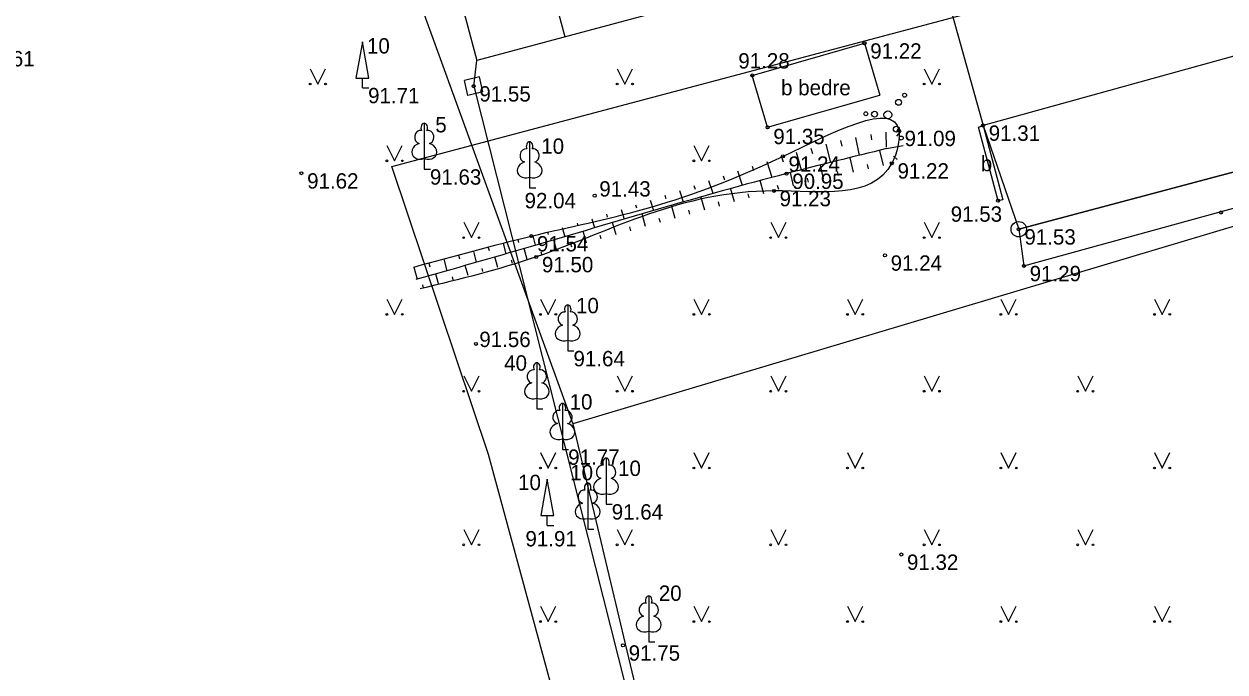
# Model space of a CAD drawing. Extents: x 634272 to 634544, y 247463 to 247653.
# Drawn here: x 634375.43 to 634414.55, y 247510.86 to 247531.95 of the extents above; entities that cross this region are included whole.
import ezdxf

# ---------------------------------------------------------------- set-up
doc = ezdxf.new("R2010")
doc.units = 0
for name, color, linetype in [('BUVE_BALK_####_####_#', 7, 'Continuous'), ('BUVE_BDET_####_####_#', 7, 'Continuous'), ('BUVE_BDET_####_TKST_#', 7, 'Continuous'), ('BUVE_EKAS_####_####_#', 7, 'Continuous'), ('BUVE_ELEM_####_####_#', 7, 'Continuous'), ('NORB_ELEM_####_####_#', 7, 'Continuous'), ('NORB_ZOGS_SBST_####_#', 7, 'Continuous'), ('NORB_ZOGS_ZSTP_####_#', 7, 'Continuous'), ('RAMI_UZMR_####_####_#', 7, 'Continuous'), ('RELJ_AATZ_####_TKST_#', 7, 'Continuous'), ('RELJ_ELEM_####_####_#', 7, 'Continuous'), ('RELJ_NOGA_####_####_#', 7, 'Continuous'), ('RELJ_NOGL_####_####_#', 7, 'Continuous'), ('ROBZ_PROJ_####_####_#', 7, 'Continuous'), ('ROBZ_UZMR_####_####_#', 7, 'Continuous'), ('TERT_DIAM_####_TKST_#', 7, 'Continuous'), ('TERT_ELEM_####_####_#', 7, 'Continuous')]:
    doc.layers.add(name, color=color, linetype=linetype)

msp = doc.modelspace()

# ---------------------------------------------------------------- linework, layer by layer
at = {"layer": 'BUVE_BALK_####_####_#'}
for points in [[(634407.83, 247525.273), (634432.599, 247531.864)], [(634406.667, 247528.651), (634407.83, 247525.273)]]:
    msp.add_lwpolyline(points, dxfattribs=at)
at = {"layer": 'BUVE_BDET_####_####_#'}
for p in [(634402.807, 247531.326), (634399.65, 247528.593)]:
    msp.add_line(p, (634403.305, 247529.64), dxfattribs=at)
for points in [[(634408.001, 247524.08), (634432.864, 247530.914), (634432.599, 247531.864), (634407.83, 247525.273), (634408.001, 247524.08)], [(634399.65, 247528.593), (634399.152, 247530.279), (634402.807, 247531.326)], [(634406.667, 247528.651), (634407.314, 247526.226), (634407.157, 247526.202), (634406.522, 247528.597), (634406.667, 247528.651)]]:
    msp.add_lwpolyline(points, dxfattribs=at)
at = {"layer": 'BUVE_EKAS_####_####_#'}
for q in [(634390.179, 247530.767), (634406.667, 247528.651)]:
    msp.add_line((634404.984, 247534.73), q, dxfattribs=at)
for points in [[(634427.366, 247549.085), (634431.438, 247535.508), (634406.667, 247528.651)], [(634390.958, 247539.332), (634393.045, 247531.534)], [(634388.101, 247538.53), (634390.179, 247530.767)]]:
    msp.add_lwpolyline(points, dxfattribs=at)
at = {"layer": 'BUVE_ELEM_####_####_#'}
msp.add_circle((634407.83, 247525.273), 0.25, dxfattribs=at)
at = {"layer": 'NORB_ELEM_####_####_#'}
for p, q in [((634390.262, 247530.231), (634389.775, 247530.116)), ((634390.377, 247529.744), (634390.262, 247530.231)), ((634389.89, 247529.629), (634389.775, 247530.116)), ((634390.377, 247529.744), (634389.89, 247529.629))]:
    msp.add_line(p, q, dxfattribs=at)
msp.add_circle((634390.076, 247529.93), 0.0504, dxfattribs=at)
at = {"layer": 'NORB_ZOGS_SBST_####_#'}
msp.add_lwpolyline([(634390.076, 247529.93), (634397.008, 247502.541)], dxfattribs=at)
at = {"layer": 'NORB_ZOGS_ZSTP_####_#'}
msp.add_lwpolyline([(634390.076, 247529.93), (634390.179, 247530.767)], dxfattribs=at)
at = {"layer": 'RAMI_UZMR_####_####_#'}
msp.add_lwpolyline([(634466.614, 247558.36), (634469.076, 247546.545), (634471.781, 247533.982), (634471.429, 247521.859), (634457.577, 247518.735), (634456.257, 247517.942), (634433.742, 247506.986), (634428.158, 247503.509), (634420.457, 247500.517), (634407.71, 247496.821), (634397.043, 247493.687), (634395.968, 247498.053), (634390.559, 247517.942), (634387.41, 247527.318), (634427.834, 247538.059), (634425.364, 247546.393), (634376.048, 247532.596), (634371.988, 247530.992)], dxfattribs=at)
at = {"layer": 'RELJ_ELEM_####_####_#'}
for centre in [(634402.807, 247531.326), (634399.152, 247530.279), (634390.076, 247529.93), (634399.65, 247528.593), (634406.667, 247528.651), (634403.925, 247528.48), (634400.145, 247527.645), (634403.696, 247527.422), (634384.465, 247527.096), (634400.267, 247527.085), (634394.019, 247526.366), (634399.854, 247526.521), (634407.157, 247526.202), (634414.415, 247525.819), (634391.952, 247525.05), (634407.83, 247525.273), (634392.113, 247524.371), (634403.472, 247524.422), (634408.001, 247524.08), (634390.147, 247521.54), (634404.004, 247514.685), (634394.939, 247511.728)]:
    msp.add_circle(centre, 0.05, dxfattribs=at)
at = {"layer": 'RELJ_NOGA_####_####_#'}
for p, q in [((634402.517, 247528.264), (634402.636, 247527.676)), ((634403.009, 247528.356), (634403.037, 247528.187)), ((634403.503, 247528.431), (634403.512, 247527.946)), ((634403.861, 247528.301), (634403.998, 247528.468)), ((634403.953, 247528.48), (634403.953, 247528.48)), ((634401.059, 247527.914), (634401.108, 247527.737)), ((634401.542, 247528.042), (634401.695, 247527.441)), ((634402.028, 247528.159), (634402.069, 247527.979)), ((634403.422, 247527.352), (634403.301, 247527.841)), ((634403.524, 247527.897), (634404.068, 247528.001)), ((634404.078, 247528.047), (634404.077, 247528.047)), ((634399.623, 247527.48), (634399.788, 247526.964)), ((634400.1, 247527.631), (634400.152, 247527.467)), ((634400.578, 247527.777), (634400.748, 247527.205)), ((634402.448, 247527.127), (634402.343, 247527.603)), ((634403.869, 247527.547), (634403.747, 247527.648)), ((634403.897, 247527.585), (634403.897, 247527.585)), ((634398.672, 247527.17), (634398.824, 247526.709)), ((634399.148, 247527.326), (634399.195, 247527.18)), ((634400.496, 247526.688), (634400.392, 247527.116)), ((634401.471, 247526.912), (634401.372, 247527.361)), ((634401.959, 247527.02), (634401.929, 247527.158)), ((634402.935, 247527.236), (634402.902, 247527.382)), ((634397.249, 247526.696), (634397.288, 247526.58)), ((634397.723, 247526.855), (634397.861, 247526.443)), ((634398.198, 247527.013), (634398.241, 247526.882)), ((634399.53, 247526.431), (634399.409, 247526.865)), ((634400.012, 247526.564), (634399.977, 247526.692)), ((634400.983, 247526.804), (634400.953, 247526.934)), ((634396.301, 247526.38), (634396.336, 247526.274)), ((634396.775, 247526.538), (634396.898, 247526.169)), ((634397.603, 247525.894), (634397.48, 247526.336)), ((634398.567, 247526.163), (634398.443, 247526.605)), ((634399.048, 247526.297), (634399.012, 247526.429)), ((634394.875, 247525.913), (634394.974, 247525.603)), ((634395.351, 247526.067), (634395.382, 247525.97)), ((634395.826, 247526.222), (634395.936, 247525.888)), ((634396.64, 247525.626), (634396.519, 247526.059)), ((634397.122, 247525.76), (634397.085, 247525.892)), ((634398.085, 247526.029), (634398.048, 247526.162)), ((634393.442, 247525.47), (634393.469, 247525.381)), ((634393.921, 247525.614), (634394.012, 247525.317)), ((634394.398, 247525.762), (634394.427, 247525.671)), ((634394.713, 247525.09), (634394.601, 247525.492)), ((634395.677, 247525.358), (634395.56, 247525.776)), ((634396.158, 247525.492), (634396.123, 247525.62)), ((634392.481, 247525.193), (634392.506, 247525.102)), ((634392.962, 247525.329), (634393.048, 247525.031)), ((634393.75, 247524.822), (634393.643, 247525.207)), ((634394.231, 247524.956), (634394.199, 247525.074)), ((634395.195, 247525.224), (634395.161, 247525.347)), ((634390.548, 247524.68), (634390.575, 247524.576)), ((634391.032, 247524.807), (634391.12, 247524.473)), ((634391.515, 247524.935), (634391.541, 247524.838)), ((634391.999, 247525.062), (634392.082, 247524.75)), ((634392.786, 247524.556), (634392.684, 247524.925)), ((634393.268, 247524.689), (634393.237, 247524.802)), ((634389.098, 247524.297), (634389.197, 247523.921)), ((634389.581, 247524.425), (634389.61, 247524.315)), ((634390.065, 247524.552), (634390.158, 247524.197)), ((634390.857, 247524.026), (634390.763, 247524.371)), ((634391.822, 247524.291), (634391.724, 247524.647)), ((634392.304, 247524.423), (634392.274, 247524.532)), ((634388.131, 247524.042), (634388.236, 247523.645)), ((634388.614, 247524.17), (634388.645, 247524.054)), ((634389.893, 247523.762), (634389.801, 247524.095)), ((634390.375, 247523.894), (634390.347, 247523.996)), ((634391.339, 247524.159), (634391.311, 247524.264)), ((634388.928, 247523.497), (634388.84, 247523.819)), ((634389.411, 247523.629), (634389.384, 247523.728)), ((634388.446, 247523.365), (634388.42, 247523.459))]:
    msp.add_line(p, q, dxfattribs=at)
msp.add_spline([(634388.131, 247524.042), (634391.952, 247525.05), (634400.145, 247527.645), (634403.925, 247528.48), (634403.696, 247527.422), (634399.854, 247526.521), (634392.113, 247524.371), (634388.335, 247523.334)], degree=3, dxfattribs=at)
at = {"layer": 'RELJ_NOGL_####_####_#'}
msp.add_spline([(634403.524, 247527.897), (634400.267, 247527.085), (634391.92, 247524.703), (634388.194, 247523.633)], degree=3, dxfattribs=at)
at = {"layer": 'ROBZ_PROJ_####_####_#'}
msp.add_lwpolyline([(634393.309, 247518.933), (634397.146, 247502.796)], dxfattribs=at)
at = {"layer": 'ROBZ_UZMR_####_####_#'}
for points in [[(634385.149, 247541.391), (634393.309, 247518.933)], [(634435.861, 247531.644), (634393.309, 247518.933)]]:
    msp.add_lwpolyline(points, dxfattribs=at)
at = {"layer": 'TERT_ELEM_####_####_#'}
for p, q in [((634384.75, 247530.5), (634385, 247530)), ((634385, 247530), (634385.25, 247530.5)), ((634386.451, 247529.875), (634386.451, 247530.195)), ((634394.75, 247530.5), (634395, 247530)), ((634395, 247530), (634395.25, 247530.5)), ((634404.75, 247530.5), (634405, 247530)), ((634405, 247530), (634405.25, 247530.5)), ((634386.451, 247529.875), (634386.661, 247529.875)), ((634387.25, 247528), (634387.5, 247527.5)), ((634387.5, 247527.5), (634387.75, 247528)), ((634397.25, 247528), (634397.5, 247527.5)), ((634397.5, 247527.5), (634397.75, 247528)), ((634388.465, 247527.571), (634388.465, 247527.224)), ((634388.465, 247527.224), (634388.665, 247527.224)), ((634391.896, 247526.967), (634391.896, 247526.62)), ((634391.896, 247526.62), (634392.096, 247526.62)), ((634389.75, 247525.5), (634390, 247525)), ((634390, 247525), (634390.25, 247525.5)), ((634399.75, 247525.5), (634400, 247525)), ((634400, 247525), (634400.25, 247525.5)), ((634404.75, 247525.5), (634405, 247525)), ((634405, 247525), (634405.25, 247525.5)), ((634387.25, 247523), (634387.5, 247522.5)), ((634387.5, 247522.5), (634387.75, 247523)), ((634392.25, 247523), (634392.5, 247522.5)), ((634392.5, 247522.5), (634392.75, 247523)), ((634397.25, 247523), (634397.5, 247522.5)), ((634397.5, 247522.5), (634397.75, 247523)), ((634402.25, 247523), (634402.5, 247522.5)), ((634402.5, 247522.5), (634402.75, 247523)), ((634407.25, 247523), (634407.5, 247522.5)), ((634407.5, 247522.5), (634407.75, 247523)), ((634412.25, 247523), (634412.5, 247522.5)), ((634412.5, 247522.5), (634412.75, 247523)), ((634393.141, 247521.658), (634393.141, 247521.311)), ((634393.141, 247521.311), (634393.341, 247521.311)), ((634389.75, 247520.5), (634390, 247520)), ((634390, 247520), (634390.25, 247520.5)), ((634394.75, 247520.5), (634395, 247520)), ((634395, 247520), (634395.25, 247520.5)), ((634399.75, 247520.5), (634400, 247520)), ((634400, 247520), (634400.25, 247520.5)), ((634404.75, 247520.5), (634405, 247520)), ((634405, 247520), (634405.25, 247520.5)), ((634409.75, 247520.5), (634410, 247520)), ((634410, 247520), (634410.25, 247520.5)), ((634392.133, 247519.774), (634392.133, 247519.427)), ((634392.133, 247519.427), (634392.333, 247519.427)), ((634392.968, 247518.451), (634392.968, 247518.104)), ((634392.968, 247518.104), (634393.168, 247518.104)), ((634392.25, 247518), (634392.5, 247517.5)), ((634392.5, 247517.5), (634392.75, 247518)), ((634397.25, 247518), (634397.5, 247517.5)), ((634397.5, 247517.5), (634397.75, 247518)), ((634402.25, 247518), (634402.5, 247517.5)), ((634402.5, 247517.5), (634402.75, 247518)), ((634407.25, 247518), (634407.5, 247517.5)), ((634407.5, 247517.5), (634407.75, 247518)), ((634412.25, 247518), (634412.5, 247517.5)), ((634412.5, 247517.5), (634412.75, 247518)), ((634394.387, 247516.669), (634394.387, 247516.322)), ((634394.387, 247516.322), (634394.587, 247516.322)), ((634392.474, 247515.633), (634392.474, 247515.953)), ((634393.79, 247515.861), (634393.79, 247515.514)), ((634389.75, 247515.5), (634390, 247515)), ((634390, 247515), (634390.25, 247515.5)), ((634392.474, 247515.633), (634392.684, 247515.633)), ((634393.79, 247515.514), (634393.99, 247515.514)), ((634394.75, 247515.5), (634395, 247515)), ((634395, 247515), (634395.25, 247515.5)), ((634399.75, 247515.5), (634400, 247515)), ((634400, 247515), (634400.25, 247515.5)), ((634404.75, 247515.5), (634405, 247515)), ((634405, 247515), (634405.25, 247515.5)), ((634409.75, 247515.5), (634410, 247515)), ((634410, 247515), (634410.25, 247515.5)), ((634392.25, 247513), (634392.5, 247512.5)), ((634392.5, 247512.5), (634392.75, 247513)), ((634397.25, 247513), (634397.5, 247512.5)), ((634397.5, 247512.5), (634397.75, 247513)), ((634402.25, 247513), (634402.5, 247512.5)), ((634402.5, 247512.5), (634402.75, 247513)), ((634407.25, 247513), (634407.5, 247512.5)), ((634407.5, 247512.5), (634407.75, 247513)), ((634412.25, 247513), (634412.5, 247512.5)), ((634412.5, 247512.5), (634412.75, 247513)), ((634395.779, 247512.184), (634395.779, 247511.837)), ((634395.779, 247511.837), (634395.979, 247511.837))]:
    msp.add_line(p, q, dxfattribs=at)
for points in [[(634386.241, 247530.195), (634386.661, 247530.195), (634386.451, 247531.375)], [(634392.264, 247515.953), (634392.684, 247515.953), (634392.474, 247517.133)]]:
    msp.add_lwpolyline(points, close=True, dxfattribs=at)
for points in [[(634388.465, 247528.724), (634388.465, 247527.571)], [(634388.555, 247528.492), (634388.554, 247528.493)], [(634391.896, 247528.12), (634391.896, 247526.967)], [(634391.986, 247527.888), (634391.985, 247527.889)], [(634393.141, 247522.811), (634393.141, 247521.658)], [(634393.231, 247522.579), (634393.23, 247522.58)], [(634392.133, 247520.927), (634392.133, 247519.774)], [(634392.223, 247520.695), (634392.222, 247520.696)], [(634392.968, 247519.604), (634392.968, 247518.451)], [(634393.058, 247519.372), (634393.057, 247519.373)], [(634394.387, 247517.822), (634394.387, 247516.669)], [(634394.477, 247517.59), (634394.476, 247517.591)], [(634393.79, 247517.014), (634393.79, 247515.861)], [(634393.88, 247516.782), (634393.879, 247516.783)], [(634395.779, 247513.337), (634395.779, 247512.184)], [(634395.869, 247513.105), (634395.868, 247513.106)]]:
    msp.add_lwpolyline(points, dxfattribs=at)
for centre, radius in [((634384.75, 247530), 0.028), ((634385.25, 247530), 0.0263), ((634394.75, 247530), 0.028), ((634395.25, 247530), 0.0263), ((634404.75, 247530), 0.028), ((634405.25, 247530), 0.0263), ((634403.916, 247529.406), 0.096), ((634404.112, 247529.637), 0.064), ((634402.85, 247529.032), 0.064), ((634403.134, 247529.019), 0.096), ((634403.568, 247528.998), 0.128), ((634403.844, 247528.531), 0.096), ((634404.002, 247528.242), 0.064), ((634387.25, 247527.5), 0.028), ((634387.75, 247527.5), 0.0263), ((634397.25, 247527.5), 0.028), ((634397.75, 247527.5), 0.0263), ((634389.75, 247525), 0.028), ((634390.25, 247525), 0.0263), ((634399.75, 247525), 0.028), ((634400.25, 247525), 0.0263), ((634404.75, 247525), 0.028), ((634405.25, 247525), 0.0263), ((634387.25, 247522.5), 0.028), ((634387.75, 247522.5), 0.0263), ((634392.25, 247522.5), 0.028), ((634392.75, 247522.5), 0.0263), ((634397.25, 247522.5), 0.028), ((634397.75, 247522.5), 0.0263), ((634402.25, 247522.5), 0.028), ((634402.75, 247522.5), 0.0263), ((634407.25, 247522.5), 0.028), ((634407.75, 247522.5), 0.0263), ((634412.25, 247522.5), 0.028), ((634412.75, 247522.5), 0.0263), ((634389.75, 247520), 0.028), ((634390.25, 247520), 0.0263), ((634394.75, 247520), 0.028), ((634395.25, 247520), 0.0263), ((634399.75, 247520), 0.028), ((634400.25, 247520), 0.0263), ((634404.75, 247520), 0.028), ((634405.25, 247520), 0.0263), ((634409.75, 247520), 0.028), ((634410.25, 247520), 0.0263), ((634392.25, 247517.5), 0.028), ((634392.75, 247517.5), 0.0263), ((634397.25, 247517.5), 0.028), ((634397.75, 247517.5), 0.0263), ((634402.25, 247517.5), 0.028), ((634402.75, 247517.5), 0.0263), ((634407.25, 247517.5), 0.028), ((634407.75, 247517.5), 0.0263), ((634412.25, 247517.5), 0.028), ((634412.75, 247517.5), 0.0263), ((634389.75, 247515), 0.028), ((634390.25, 247515), 0.0263), ((634394.75, 247515), 0.028), ((634395.25, 247515), 0.0263), ((634399.75, 247515), 0.028), ((634400.25, 247515), 0.0263), ((634404.75, 247515), 0.028), ((634405.25, 247515), 0.0263), ((634409.75, 247515), 0.028), ((634410.25, 247515), 0.0263), ((634392.25, 247512.5), 0.028), ((634392.75, 247512.5), 0.0263), ((634397.25, 247512.5), 0.028), ((634397.75, 247512.5), 0.0263), ((634402.25, 247512.5), 0.028), ((634402.75, 247512.5), 0.0263), ((634407.25, 247512.5), 0.028), ((634407.75, 247512.5), 0.0263), ((634412.25, 247512.5), 0.028), ((634412.75, 247512.5), 0.0263)]:
    msp.add_circle(centre, radius, dxfattribs=at)
for centre, major_axis, ratio, start_param, end_param in [((634388.465, 247528.574), (0, -0.15), 0.707107, 3.14537, 5.287485), ((634388.465, 247528.574), (0, -0.15), 0.707107, 0.995701, 3.137816), ((634388.337, 247528.279), (-0.039, -0.212), 0.861323, 3.141593, 6.283185), ((634388.593, 247528.279), (0.039, -0.212), 0.861323, 0, 3.141593), ((634388.375, 247527.817), (0.307, 0.095), 0.814445, 1.570796, 4.752015), ((634388.555, 247527.817), (-0.307, 0.095), 0.814445, 1.531171, 4.712389), ((634391.768, 247527.675), (-0.039, -0.212), 0.861323, 3.141593, 6.283185), ((634391.896, 247527.97), (0, -0.15), 0.707107, 3.14537, 5.287485), ((634391.896, 247527.97), (0, -0.15), 0.707107, 0.995701, 3.137816), ((634392.024, 247527.675), (0.039, -0.212), 0.861323, 0, 3.141593), ((634391.806, 247527.213), (0.307, 0.095), 0.814445, 1.570796, 4.752015), ((634391.986, 247527.213), (-0.307, 0.095), 0.814445, 1.531171, 4.712389), ((634393.141, 247522.661), (0, -0.15), 0.707107, 3.14537, 5.287485), ((634393.141, 247522.661), (0, -0.15), 0.707107, 0.995701, 3.137816), ((634393.013, 247522.366), (-0.039, -0.212), 0.861323, 3.141593, 6.283185), ((634393.269, 247522.366), (0.039, -0.212), 0.861323, 0, 3.141593), ((634393.051, 247521.904), (0.307, 0.095), 0.814445, 1.570796, 4.752015), ((634393.231, 247521.904), (-0.307, 0.095), 0.814445, 1.531171, 4.712389), ((634392.133, 247520.777), (0, -0.15), 0.707107, 3.14537, 5.287485), ((634392.133, 247520.777), (0, -0.15), 0.707107, 0.995701, 3.137816), ((634392.005, 247520.482), (-0.039, -0.212), 0.861323, 3.141593, 6.283185), ((634392.261, 247520.482), (0.039, -0.212), 0.861323, 0, 3.141593), ((634392.043, 247520.02), (0.307, 0.095), 0.814445, 1.570796, 4.752015), ((634392.223, 247520.02), (-0.307, 0.095), 0.814445, 1.531171, 4.712389), ((634392.968, 247519.454), (0, -0.15), 0.707107, 3.14537, 5.287485), ((634392.968, 247519.454), (0, -0.15), 0.707107, 0.995701, 3.137816), ((634392.84, 247519.159), (-0.039, -0.212), 0.861323, 3.141593, 6.283185), ((634393.096, 247519.159), (0.039, -0.212), 0.861323, 0, 3.141593), ((634392.878, 247518.697), (0.307, 0.095), 0.814445, 1.570796, 4.752015), ((634393.058, 247518.697), (-0.307, 0.095), 0.814445, 1.531171, 4.712389), ((634394.387, 247517.672), (0, -0.15), 0.707107, 3.14537, 5.287485), ((634394.387, 247517.672), (0, -0.15), 0.707107, 0.995701, 3.137816), ((634394.259, 247517.377), (-0.039, -0.212), 0.861323, 3.141593, 6.283185), ((634394.515, 247517.377), (0.039, -0.212), 0.861323, 0, 3.141593), ((634393.79, 247516.864), (0, -0.15), 0.707107, 3.14537, 5.287485), ((634393.79, 247516.864), (0, -0.15), 0.707107, 0.995701, 3.137816), ((634394.297, 247516.915), (0.307, 0.095), 0.814445, 1.570796, 4.752015), ((634394.477, 247516.915), (-0.307, 0.095), 0.814445, 1.531171, 4.712389), ((634393.662, 247516.569), (-0.039, -0.212), 0.861323, 3.141593, 6.283185), ((634393.918, 247516.569), (0.039, -0.212), 0.861323, 0, 3.141593), ((634393.7, 247516.107), (0.307, 0.095), 0.814445, 1.570796, 4.752015), ((634393.88, 247516.107), (-0.307, 0.095), 0.814445, 1.531171, 4.712389), ((634395.779, 247513.187), (0, -0.15), 0.707107, 3.14537, 5.287485), ((634395.779, 247513.187), (0, -0.15), 0.707107, 0.995701, 3.137816), ((634395.651, 247512.892), (-0.039, -0.212), 0.861323, 3.141593, 6.283185), ((634395.907, 247512.892), (0.039, -0.212), 0.861323, 0, 3.141593), ((634395.689, 247512.43), (0.307, 0.095), 0.814445, 1.570796, 4.752015), ((634395.869, 247512.43), (-0.307, 0.095), 0.814445, 1.531171, 4.712389)]:
    msp.add_ellipse(centre, major_axis=major_axis, ratio=ratio, start_param=start_param, end_param=end_param, dxfattribs=at)

# ---------------------------------------------------------------- texts
at = {"layer": 'BUVE_BDET_####_TKST_#'}
for s, p in [('b bedre', (634400.089, 247529.633)), ('b', (634406.595, 247527.161))]:
    msp.add_text(s, height=0.5, dxfattribs=at).set_placement(p)
at = {"layer": 'RELJ_AATZ_####_TKST_#'}
for s, p in [(' 91.22', (634402.807, 247530.826)), (' 91.61', (634373.916, 247530.575)), (' 91.28', (634398.51, 247530.506)), (' 91.71', (634386.451, 247529.375)), (' 91.71', (634386.451, 247529.375)), (' 91.55', (634390.076, 247529.43)), (' 91.31', (634406.667, 247528.151)), (' 91.35', (634399.65, 247528.043)), (' 91.09', (634403.925, 247527.98)), (' 91.24', (634400.145, 247527.145)), (' 91.22', (634403.696, 247526.922)), (' 91.62', (634384.465, 247526.596)), (' 91.63', (634388.465, 247526.724)), (' 90.95', (634400.267, 247526.585)), (' 91.43', (634393.982, 247526.337)), (' 92.04', (634391.548, 247525.955)), (' 91.23', (634399.854, 247526.021)), (' 91.53', (634405.429, 247525.518)), (' 91.53', (634407.83, 247524.773)), (' 91.54', (634391.952, 247524.55)), (' 91.50', (634392.113, 247523.871)), (' 91.24', (634403.472, 247523.922)), (' 91.29', (634408.001, 247523.58)), (' 91.56', (634390.074, 247521.438)), (' 91.64', (634393.141, 247520.811)), (' 91.77', (634392.968, 247517.604)), (' 91.64', (634394.387, 247515.822)), (' 91.91', (634391.576, 247514.948)), (' 91.32', (634404.004, 247514.185)), (' 91.75', (634394.939, 247511.228))]:
    msp.add_text(s, height=0.5, dxfattribs=at).set_placement(p)
at = {"layer": 'TERT_DIAM_####_TKST_#'}
for s, p in [('10', (634386.599, 247530.994)), ('5', (634388.825, 247528.427)), ('10', (634392.277, 247527.729)), ('10', (634393.409, 247522.538)), ('40', (634391.069, 247520.669)), ('10', (634393.201, 247519.404)), ('10', (634394.779, 247517.241)), ('10', (634391.522, 247516.78)), ('10', (634393.22, 247517.101)), ('20', (634396.106, 247513.175))]:
    msp.add_text(s, height=0.5, dxfattribs=at).set_placement(p)

doc.saveas('drawing.dxf')
